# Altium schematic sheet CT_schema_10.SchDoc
size 278 x 170 mm
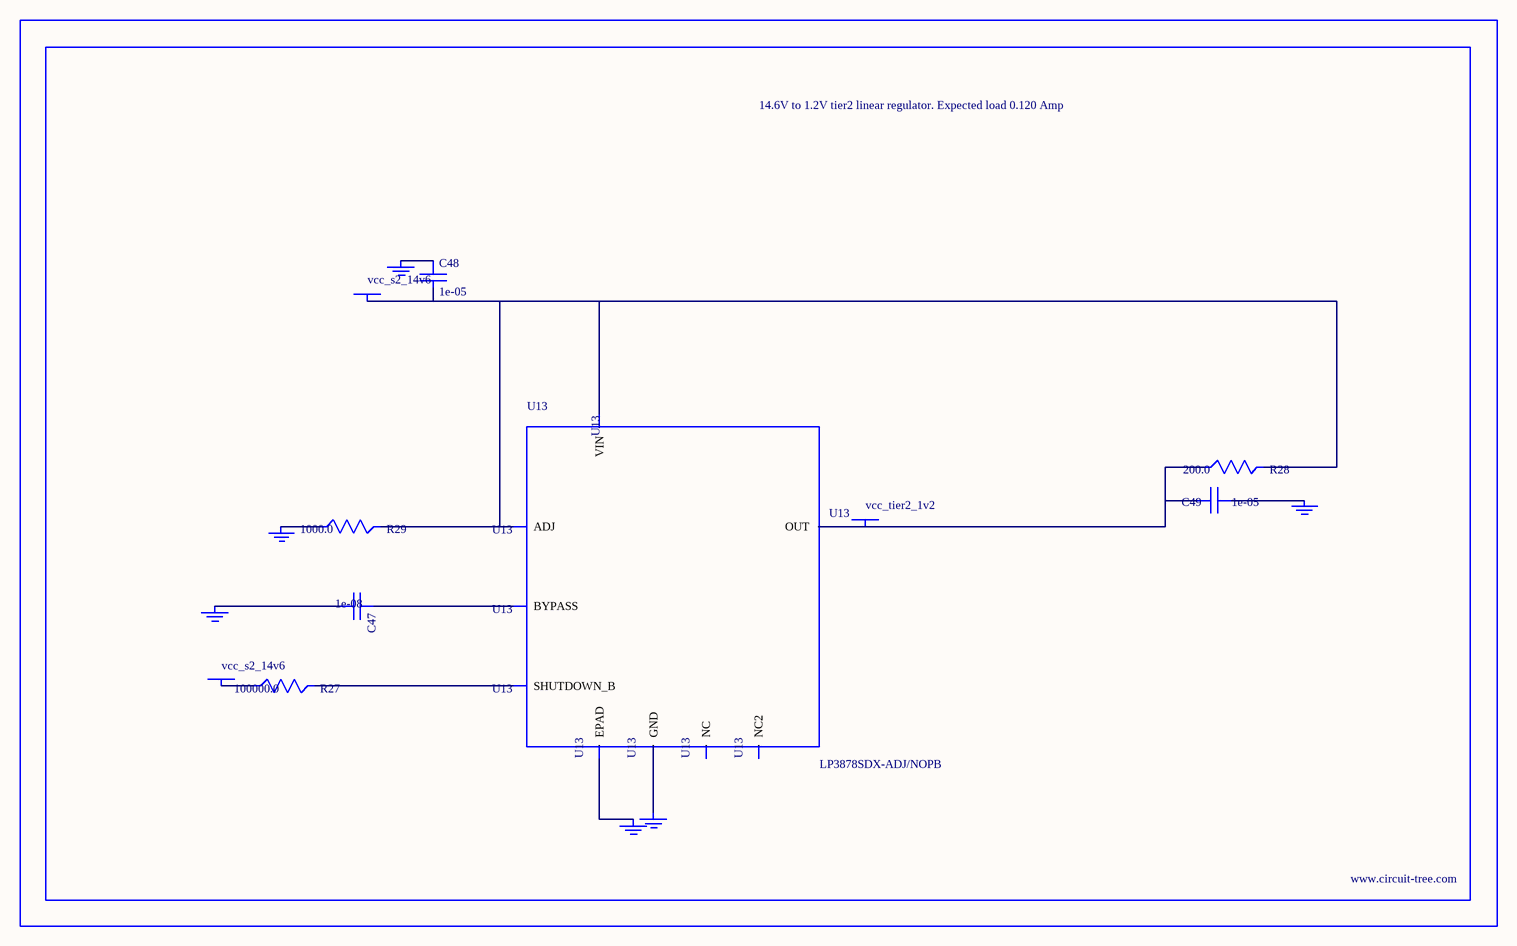
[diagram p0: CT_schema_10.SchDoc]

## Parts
BORDER9  (no value)
C47  1e-08  [C0402]
C48  1e-05  [C1210]
C49  1e-05  [C0805]
GND_INSTANCE_9_0  (no value)
GND_INSTANCE_9_1  (no value)
GND_INSTANCE_9_2  (no value)
GND_INSTANCE_9_3  (no value)
GND_INSTANCE_9_4  (no value)
GND_INSTANCE_9_5  (no value)
POWER_INSTANCE_9_0  vcc_s2_14v6
POWER_INSTANCE_9_1  vcc_s2_14v6
POWER_INSTANCE_9_2  vcc_tier2_1v2
R27  100000.0  [R0603]
R28  200.0  [R0603]
R29  1000.0  [R0603]
U13  LP3878SDX-ADJ/NOPB  [WSON-8]

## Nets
NetC47_1: C47.1 U13.1(BYPASS)
NetC47_2: C47.2 GND_INSTANCE_9_0.0(GND)
NetC48_1: C48.1 GND_INSTANCE_9_1.0(GND)
NetC48_2: C48.2 POWER_INSTANCE_9_0.0(PWR) R28.2 R29.2 U13.4(VIN) U13.6(ADJ)
NetC49_1: C49.1 GND_INSTANCE_9_2.0(GND)
NetC49_2: C49.2 POWER_INSTANCE_9_2.0(PWR) R28.1 U13.5(OUT)
NetGND_INSTANCE_9_3_0: GND_INSTANCE_9_3.0(GND) R29.1
NetGND_INSTANCE_9_4_0: GND_INSTANCE_9_4.0(GND) U13.PAD(EPAD)
NetGND_INSTANCE_9_5_0: GND_INSTANCE_9_5.0(GND) U13.3(GND)
NetPOWER_INSTANCE_9_1_0: POWER_INSTANCE_9_1.0(PWR) R27.1
NetR27_2: R27.2 U13.8(SHUTDOWN_B)

Not connected (* = marked no-connect by the designer): U13 2(NC) 7(NC2)

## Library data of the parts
BORDER9 = BORDER_PAGE9
C47 = C0402C103K3RAC
C48 = C1210C106K5PACTU
C49 = GRM219R60J106ME19D
GND_INSTANCE_9_0-GND_INSTANCE_9_5 = GND
POWER_INSTANCE_9_0-POWER_INSTANCE_9_2 = PWR
R27 = RC0603JR-07100KL
R28 = RC0603JR-07200RL
R29 = RC0603JR-071KL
